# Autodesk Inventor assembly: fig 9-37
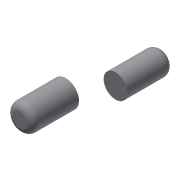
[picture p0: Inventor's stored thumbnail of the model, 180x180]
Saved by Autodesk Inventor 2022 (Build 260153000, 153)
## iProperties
Created: 2013-07
Part Number: fig 9-37
Document SubType Name: Assembly
Designer: CADCIM
Author: CADCIM
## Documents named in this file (3)
- D:\PROJECTS_2021\Resources\Part Files\c09_Inv_2022_prt\fig 9-38.iam
- D:\PROJECTS_2021\Resources\Part Files\c09_Inv_2022_prt\10.ipt
- D:\PROJECTS_2021\Resources\Part Files\c09_Inv_2022_prt\11.ipt
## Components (2 placed, 2 different names)
1. 10:1
2. 11:1
